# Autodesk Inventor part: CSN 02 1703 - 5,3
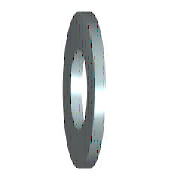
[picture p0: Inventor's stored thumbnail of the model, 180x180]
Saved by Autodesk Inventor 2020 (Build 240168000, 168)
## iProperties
Created: 2019-01
Part Number: CSN 02 1703 - 5,3
Material: Ocel, měkká
Description: Podložky pro šrouby s válcovou a půlkulovou hlavou
Document SubType Name: Modeling
Standard: CSN 02 1703
Designer: doma
Standards Organization: CSN
Language: cs-CZ
Size Designation: 5,3
Categories: <MemberInstance><Categories><Category DisplayName="Spojovací materiál" InternalName="e4da775c-781d-43d5-af7c-5136215cf5a6" Mnemonic="FSTN"><Category DisplayName
Density: 7.85 g/cm^3
Appearance: Pololeštěná
IsCustomPart: 0
Author: doma
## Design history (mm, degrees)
sketch "Náčrt"
  geometry: C1 r 4.75 at (0, 0); C2 r 2.65 at (0, 0); 1 further point
  constraints: 2 centre point, 2 coincident
  dimensions: "d0" = 5.3 diameter of C2 (= SD1); "d1" = 9.5 diameter of C1 (= SD2)
extrude "Těleso" new body sketch "Náčrt" distance "d2" = 1 (= SD); taper "d3" = 0 deg
workaxis "Work Axis1"
workplane "Work Plane1"
body "Solid1"
other parameters: "SD1" = 5.3 [user parameter; used in 1 equation term], "SD2" = 9.5 [user parameter; used in 1 equation term], "SD" = 1 [user parameter; used in 1 equation term], "d4" = 0, "d5" = 0, "d6" = 0, "d7" = 0, "NND" = 5 [user parameter]
